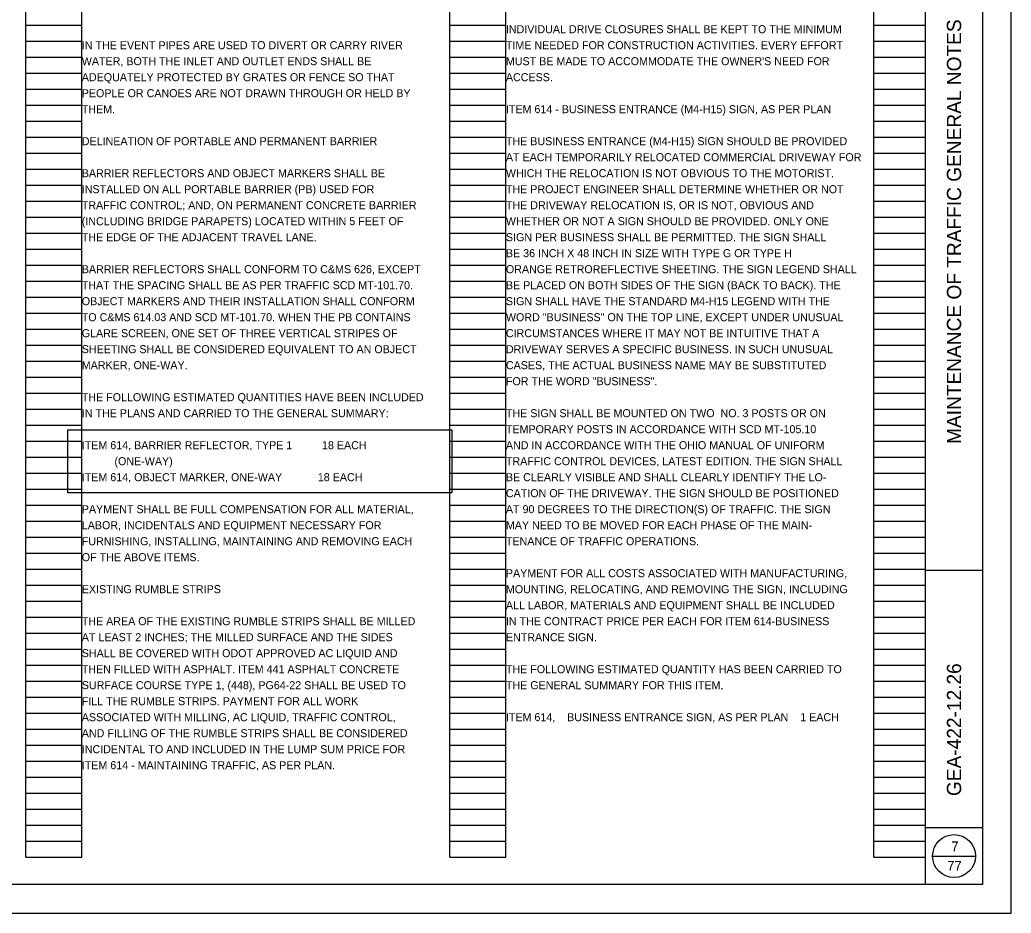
# Model space of a CAD drawing. Extents: x 0 to 34, y 0 to 27.5.
# Drawn here: x 16.66 to 34, y 0 to 15.63 of the extents above; entities that cross this region are included whole.
import ezdxf

# ---------------------------------------------------------------- set-up
doc = ezdxf.new("R2010")
doc.units = 0
for name, color, linetype in [('SC_Scratch1', 7, 'Continuous'), ('SH_Border', 7, 'Continuous'), ('SH_Cut_Line', 7, 'Continuous'), ('SH_Data', 7, 'Continuous'), ('SH_Text', 7, 'Continuous')]:
    doc.layers.add(name, color=color, linetype=linetype)

msp = doc.modelspace()

# ---------------------------------------------------------------- linework, layer by layer
at = {"layer": 'SC_Scratch1'}
for p, q in [((16.76, 0.98), (16.76, 21.14)), ((17.74, 0.98), (17.74, 21.14)), ((24.18, 0.98), (24.18, 21.14)), ((25.16, 0.98), (25.16, 21.14)), ((31.6, 0.98), (31.6, 21.14)), ((32.5, 0.98), (32.5, 21.14)), ((16.76, 15.54), (17.74, 15.54)), ((24.18, 15.54), (25.16, 15.54)), ((31.6, 15.54), (32.5, 15.54)), ((16.76, 15.26), (17.74, 15.26)), ((24.18, 15.26), (25.16, 15.26)), ((31.6, 15.26), (32.5, 15.26)), ((16.76, 14.98), (17.74, 14.98)), ((24.18, 14.98), (25.16, 14.98)), ((31.6, 14.98), (32.5, 14.98)), ((16.76, 14.7), (17.74, 14.7)), ((24.18, 14.7), (25.16, 14.7)), ((31.6, 14.7), (32.5, 14.7)), ((16.76, 14.42), (17.74, 14.42)), ((24.18, 14.42), (25.16, 14.42)), ((31.6, 14.42), (32.5, 14.42)), ((16.76, 14.14), (17.74, 14.14)), ((24.18, 14.14), (25.16, 14.14)), ((31.6, 14.14), (32.5, 14.14)), ((16.76, 13.86), (17.74, 13.86)), ((24.18, 13.86), (25.16, 13.86)), ((31.6, 13.86), (32.5, 13.86)), ((16.76, 13.58), (17.74, 13.58)), ((24.18, 13.58), (25.16, 13.58)), ((31.6, 13.58), (32.5, 13.58)), ((16.76, 13.3), (17.74, 13.3)), ((24.18, 13.3), (25.16, 13.3)), ((31.6, 13.3), (32.5, 13.3)), ((16.76, 13.02), (17.74, 13.02)), ((24.18, 13.02), (25.16, 13.02)), ((31.6, 13.02), (32.5, 13.02)), ((16.76, 12.74), (17.74, 12.74)), ((24.18, 12.74), (25.16, 12.74)), ((31.6, 12.74), (32.5, 12.74)), ((16.76, 12.46), (17.74, 12.46)), ((24.18, 12.46), (25.16, 12.46)), ((31.6, 12.46), (32.5, 12.46)), ((16.76, 12.18), (17.74, 12.18)), ((24.18, 12.18), (25.16, 12.18)), ((31.6, 12.18), (32.5, 12.18)), ((16.76, 11.9), (17.74, 11.9)), ((24.18, 11.9), (25.16, 11.9)), ((31.6, 11.9), (32.5, 11.9)), ((16.76, 11.62), (17.74, 11.62)), ((24.18, 11.62), (25.16, 11.62)), ((31.6, 11.62), (32.5, 11.62)), ((16.76, 11.34), (17.74, 11.34)), ((24.18, 11.34), (25.16, 11.34)), ((31.6, 11.34), (32.5, 11.34)), ((16.76, 11.06), (17.74, 11.06)), ((24.18, 11.06), (25.16, 11.06)), ((31.6, 11.06), (32.5, 11.06)), ((16.76, 10.78), (17.74, 10.78)), ((24.18, 10.78), (25.16, 10.78)), ((31.6, 10.78), (32.5, 10.78)), ((16.76, 10.5), (17.74, 10.5)), ((24.18, 10.5), (25.16, 10.5)), ((31.6, 10.5), (32.5, 10.5)), ((16.76, 10.22), (17.74, 10.22)), ((24.18, 10.22), (25.16, 10.22)), ((31.6, 10.22), (32.5, 10.22)), ((16.76, 9.94), (17.74, 9.94)), ((24.18, 9.94), (25.16, 9.94)), ((31.6, 9.94), (32.5, 9.94)), ((16.76, 9.66), (17.74, 9.66)), ((24.18, 9.66), (25.16, 9.66)), ((31.6, 9.66), (32.5, 9.66)), ((16.76, 9.38), (17.74, 9.38)), ((24.18, 9.38), (25.16, 9.38)), ((31.6, 9.38), (32.5, 9.38)), ((16.76, 9.1), (17.74, 9.1)), ((24.18, 9.1), (25.16, 9.1)), ((31.6, 9.1), (32.5, 9.1)), ((16.76, 8.82), (17.74, 8.82)), ((24.18, 8.82), (25.16, 8.82)), ((31.6, 8.82), (32.5, 8.82)), ((16.76, 8.54), (17.74, 8.54)), ((24.18, 8.54), (25.16, 8.54)), ((31.6, 8.54), (32.5, 8.54)), ((16.76, 8.26), (17.74, 8.26)), ((24.18, 8.26), (25.16, 8.26)), ((31.6, 8.26), (32.5, 8.26)), ((16.76, 7.98), (17.74, 7.98)), ((24.18, 7.98), (25.16, 7.98)), ((31.6, 7.98), (32.5, 7.98)), ((16.76, 7.7), (17.74, 7.7)), ((24.18, 7.7), (25.16, 7.7)), ((31.6, 7.7), (32.5, 7.7)), ((16.76, 7.42), (17.74, 7.42)), ((24.18, 7.42), (25.16, 7.42)), ((31.6, 7.42), (32.5, 7.42)), ((16.76, 7.14), (17.74, 7.14)), ((24.18, 7.14), (25.16, 7.14)), ((31.6, 7.14), (32.5, 7.14)), ((16.76, 6.86), (17.74, 6.86)), ((24.18, 6.86), (25.16, 6.86)), ((31.6, 6.86), (32.5, 6.86)), ((16.76, 6.58), (17.74, 6.58)), ((24.18, 6.58), (25.16, 6.58)), ((31.6, 6.58), (32.5, 6.58)), ((16.76, 6.3), (17.74, 6.3)), ((24.18, 6.3), (25.16, 6.3)), ((31.6, 6.3), (32.5, 6.3)), ((16.76, 6.02), (17.74, 6.02)), ((24.18, 6.02), (25.16, 6.02)), ((31.6, 6.02), (32.5, 6.02)), ((16.76, 5.74), (17.74, 5.74)), ((24.18, 5.74), (25.16, 5.74)), ((31.6, 5.74), (32.5, 5.74)), ((16.76, 5.46), (17.74, 5.46)), ((24.18, 5.46), (25.16, 5.46)), ((31.6, 5.46), (32.5, 5.46)), ((16.76, 5.18), (17.74, 5.18)), ((24.18, 5.18), (25.16, 5.18)), ((31.6, 5.18), (32.5, 5.18)), ((16.76, 4.9), (17.74, 4.9)), ((24.18, 4.9), (25.16, 4.9)), ((31.6, 4.9), (32.5, 4.9)), ((16.76, 4.62), (17.74, 4.62)), ((24.18, 4.62), (25.16, 4.62)), ((31.6, 4.62), (32.5, 4.62)), ((16.76, 4.34), (17.74, 4.34)), ((24.18, 4.34), (25.16, 4.34)), ((31.6, 4.34), (32.5, 4.34)), ((16.76, 4.06), (17.74, 4.06)), ((24.18, 4.06), (25.16, 4.06)), ((31.6, 4.06), (32.5, 4.06)), ((16.76, 3.78), (17.74, 3.78)), ((24.18, 3.78), (25.16, 3.78)), ((31.6, 3.78), (32.5, 3.78)), ((16.76, 3.5), (17.74, 3.5)), ((24.18, 3.5), (25.16, 3.5)), ((31.6, 3.5), (32.5, 3.5)), ((16.76, 3.22), (17.74, 3.22)), ((24.18, 3.22), (25.16, 3.22)), ((31.6, 3.22), (32.5, 3.22)), ((16.76, 2.94), (17.74, 2.94)), ((24.18, 2.94), (25.16, 2.94)), ((31.6, 2.94), (32.5, 2.94)), ((16.76, 2.66), (17.74, 2.66)), ((24.18, 2.66), (25.16, 2.66)), ((31.6, 2.66), (32.5, 2.66)), ((16.76, 2.38), (17.74, 2.38)), ((24.18, 2.38), (25.16, 2.38)), ((31.6, 2.38), (32.5, 2.38)), ((16.76, 2.1), (17.74, 2.1)), ((24.18, 2.1), (25.16, 2.1)), ((31.6, 2.1), (32.5, 2.1)), ((16.76, 1.82), (17.74, 1.82)), ((24.18, 1.82), (25.16, 1.82)), ((31.6, 1.82), (32.5, 1.82)), ((16.76, 1.54), (17.74, 1.54)), ((24.18, 1.54), (25.16, 1.54)), ((31.6, 1.54), (32.5, 1.54)), ((16.76, 1.26), (17.74, 1.26)), ((24.18, 1.26), (25.16, 1.26)), ((31.6, 1.26), (32.5, 1.26)), ((16.76, 0.98), (17.74, 0.98)), ((24.18, 0.98), (25.16, 0.98)), ((31.6, 0.98), (32.5, 0.98))]:
    msp.add_line(p, q, dxfattribs=at)
msp.add_lwpolyline([(17.496, 8.46), (24.212, 8.46), (24.212, 7.356), (17.496, 7.356)], close=True, dxfattribs=at)
at = {"layer": 'SH_Border'}
for p, q in [((32.5, 0.5), (32.5, 21.5)), ((32.5, 6), (33.5, 6)), ((32.5, 1.5), (33.5, 1.5))]:
    msp.add_line(p, q, dxfattribs=at)
msp.add_lwpolyline([(2, 21.5), (33.5, 21.5), (33.5, 0.5), (2, 0.5)], close=True, dxfattribs=at)
at = {"layer": 'SH_Cut_Line'}
msp.add_lwpolyline([(0, 0), (34, 0), (34, 22), (0, 22)], close=True, dxfattribs=at)
at = {"layer": 'SH_Data'}
msp.add_line((32.625, 1), (33.375, 1), dxfattribs=at)
msp.add_circle((33, 1), 0.375, dxfattribs=at)

# ---------------------------------------------------------------- texts
for s, p in [('MAINTENANCE OF TRAFFIC GENERAL NOTES', (33.125, 8.212)), (' GEA-422-12.26 ', (33.125, 1.957))]:
    msp.add_text(s, height=0.25, rotation=90, dxfattribs=at).set_placement(p)
for s, p in [('7', (32.954, 1.085)), ('77', (32.882, 0.745))]:
    msp.add_text(s, height=0.17, dxfattribs=at).set_placement(p)
at = {"layer": 'SH_Text'}
for s, p in [('INDIVIDUAL DRIVE CLOSURES SHALL BE KEPT TO THE MINIMUM ', (25.16, 15.4)), ('IN THE EVENT PIPES ARE USED TO DIVERT OR CARRY RIVER ', (17.74, 15.12)), ('TIME NEEDED FOR CONSTRUCTION ACTIVITIES. EVERY EFFORT ', (25.16, 15.12)), ('WATER, BOTH THE INLET AND OUTLET ENDS SHALL BE ', (17.74, 14.84)), ("MUST BE MADE TO ACCOMMODATE THE OWNER'S NEED FOR ", (25.16, 14.84)), ('ADEQUATELY PROTECTED BY GRATES OR FENCE SO THAT ', (17.74, 14.56)), ('ACCESS.', (25.16, 14.56)), ('PEOPLE OR CANOES ARE NOT DRAWN THROUGH OR HELD BY ', (17.74, 14.28)), ('THEM.', (17.74, 14)), ('ITEM 614 - BUSINESS ENTRANCE (M4-H15) SIGN, AS PER PLAN', (25.16, 14)), ('DELINEATION OF PORTABLE AND PERMANENT BARRIER', (17.74, 13.44)), ('THE BUSINESS ENTRANCE (M4-H15) SIGN SHOULD BE PROVIDED', (25.16, 13.44)), ('AT EACH TEMPORARILY RELOCATED COMMERCIAL DRIVEWAY FOR', (25.16, 13.16)), ('BARRIER REFLECTORS AND OBJECT MARKERS SHALL BE ', (17.74, 12.88)), ('WHICH THE RELOCATION IS NOT OBVIOUS TO THE MOTORIST.', (25.16, 12.88)), ('INSTALLED ON ALL PORTABLE BARRIER (PB) USED FOR ', (17.74, 12.6)), ('THE PROJECT ENGINEER SHALL DETERMINE WHETHER OR NOT', (25.16, 12.6)), ('TRAFFIC CONTROL; AND, ON PERMANENT CONCRETE BARRIER ', (17.74, 12.32)), ('THE DRIVEWAY RELOCATION IS, OR IS NOT, OBVIOUS AND', (25.16, 12.32)), ('(INCLUDING BRIDGE PARAPETS) LOCATED WITHIN 5 FEET OF ', (17.74, 12.04)), ('WHETHER OR NOT A SIGN SHOULD BE PROVIDED. ONLY ONE', (25.16, 12.04)), ('THE EDGE OF THE ADJACENT TRAVEL LANE.', (17.74, 11.76)), ('SIGN PER BUSINESS SHALL BE PERMITTED. THE SIGN SHALL', (25.16, 11.76)), ('BE 36 INCH X 48 INCH IN SIZE WITH TYPE G OR TYPE H', (25.16, 11.48)), ('BARRIER REFLECTORS SHALL CONFORM TO C&MS 626, EXCEPT ', (17.74, 11.2)), ('ORANGE RETROREFLECTIVE SHEETING. THE SIGN LEGEND SHALL', (25.16, 11.2)), ('THAT THE SPACING SHALL BE AS PER TRAFFIC SCD MT-101.70. ', (17.74, 10.92)), ('BE PLACED ON BOTH SIDES OF THE SIGN (BACK TO BACK). THE', (25.16, 10.92)), ('OBJECT MARKERS AND THEIR INSTALLATION SHALL CONFORM ', (17.74, 10.64)), ('SIGN SHALL HAVE THE STANDARD M4-H15 LEGEND WITH THE', (25.16, 10.64)), ('TO C&MS 614.03 AND SCD MT-101.70. WHEN THE PB CONTAINS ', (17.74, 10.36)), ('WORD "BUSINESS" ON THE TOP LINE, EXCEPT UNDER UNUSUAL', (25.16, 10.36)), ('GLARE SCREEN, ONE SET OF THREE VERTICAL STRIPES OF ', (17.74, 10.08)), ('CIRCUMSTANCES WHERE IT MAY NOT BE INTUITIVE THAT A', (25.16, 10.08)), ('SHEETING SHALL BE CONSIDERED EQUIVALENT TO AN OBJECT ', (17.74, 9.8)), ('DRIVEWAY SERVES A SPECIFIC BUSINESS. IN SUCH UNUSUAL', (25.16, 9.8)), ('MARKER, ONE-WAY.', (17.74, 9.52)), ('CASES, THE ACTUAL BUSINESS NAME MAY BE SUBSTITUTED', (25.16, 9.52)), ('FOR THE WORD "BUSINESS".', (25.16, 9.24)), ('THE FOLLOWING ESTIMATED QUANTITIES HAVE BEEN INCLUDED ', (17.74, 8.96)), ('IN THE PLANS AND CARRIED TO THE GENERAL SUMMARY:', (17.74, 8.68)), ('THE SIGN SHALL BE MOUNTED ON TWO  NO. 3 POSTS OR ON', (25.16, 8.68)), ('TEMPORARY POSTS IN ACCORDANCE WITH SCD MT-105.10', (25.16, 8.4)), ('ITEM 614, BARRIER REFLECTOR, TYPE 1          18 EACH', (17.74, 8.12)), ('AND IN ACCORDANCE WITH THE OHIO MANUAL OF UNIFORM', (25.16, 8.12)), ('           (ONE-WAY)', (17.74, 7.84)), ('TRAFFIC CONTROL DEVICES, LATEST EDITION. THE SIGN SHALL', (25.16, 7.84)), ('ITEM 614, OBJECT MARKER, ONE-WAY            18 EACH', (17.74, 7.56)), ('BE CLEARLY VISIBLE AND SHALL CLEARLY IDENTIFY THE LO-', (25.16, 7.56)), ('CATION OF THE DRIVEWAY. THE SIGN SHOULD BE POSITIONED', (25.16, 7.28)), ('PAYMENT SHALL BE FULL COMPENSATION FOR ALL MATERIAL, ', (17.74, 7)), ('AT 90 DEGREES TO THE DIRECTION(S) OF TRAFFIC. THE SIGN', (25.16, 7)), ('LABOR, INCIDENTALS AND EQUIPMENT NECESSARY FOR ', (17.74, 6.72)), ('MAY NEED TO BE MOVED FOR EACH PHASE OF THE MAIN-', (25.16, 6.72)), ('FURNISHING, INSTALLING, MAINTAINING AND REMOVING EACH ', (17.74, 6.44)), ('TENANCE OF TRAFFIC OPERATIONS.', (25.16, 6.44)), ('OF THE ABOVE ITEMS.', (17.74, 6.16)), ('PAYMENT FOR ALL COSTS ASSOCIATED WITH MANUFACTURING,', (25.16, 5.88)), ('EXISTING RUMBLE STRIPS', (17.74, 5.6)), ('MOUNTING, RELOCATING, AND REMOVING THE SIGN, INCLUDING', (25.16, 5.6)), ('ALL LABOR, MATERIALS AND EQUIPMENT SHALL BE INCLUDED', (25.16, 5.32)), ('THE AREA OF THE EXISTING RUMBLE STRIPS SHALL BE MILLED ', (17.74, 5.04)), ('IN THE CONTRACT PRICE PER EACH FOR ITEM 614-BUSINESS', (25.16, 5.04)), ('AT LEAST 2 INCHES; THE MILLED SURFACE AND THE SIDES ', (17.74, 4.76)), ('ENTRANCE SIGN.', (25.16, 4.76)), ('SHALL BE COVERED WITH ODOT APPROVED AC LIQUID AND ', (17.74, 4.48)), ('THEN FILLED WITH ASPHALT. ITEM 441 ASPHALT CONCRETE ', (17.74, 4.2)), ('THE FOLLOWING ESTIMATED QUANTITY HAS BEEN CARRIED TO', (25.16, 4.2)), ('SURFACE COURSE TYPE 1, (448), PG64-22 SHALL BE USED TO ', (17.74, 3.92)), ('THE GENERAL SUMMARY FOR THIS ITEM.', (25.16, 3.92)), ('FILL THE RUMBLE STRIPS. PAYMENT FOR ALL WORK ', (17.74, 3.64)), ('ASSOCIATED WITH MILLING, AC LIQUID, TRAFFIC CONTROL, ', (17.74, 3.36)), ('ITEM 614,    BUSINESS ENTRANCE SIGN, AS PER PLAN    1 EACH', (25.16, 3.36)), ('AND FILLING OF THE RUMBLE STRIPS SHALL BE CONSIDERED ', (17.74, 3.08)), ('INCIDENTAL TO AND INCLUDED IN THE LUMP SUM PRICE FOR ', (17.74, 2.8)), ('ITEM 614 - MAINTAINING TRAFFIC, AS PER PLAN.', (17.74, 2.52))]:
    msp.add_text(s, height=0.14, dxfattribs=at).set_placement(p)

doc.saveas('drawing.dxf')
